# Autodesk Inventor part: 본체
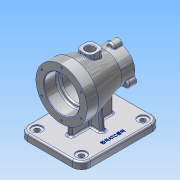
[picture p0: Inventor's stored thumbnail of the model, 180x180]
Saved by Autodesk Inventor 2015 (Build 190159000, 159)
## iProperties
Created: 2021-10
Part Number: 본체
Material: 알루미늄 6061
Document SubType Name: Modeling
Designer: 101256544
Density: 2.7 g/cm^3
Appearance: 알루미늄 - 평지
Mass: 1223.16 g
Surface Area: 900.075 cm^2
Volume: 453.022 cm^3
Author: 101256544
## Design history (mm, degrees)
sketch "스케치1"
  geometry: L1 (0, 77.575)-(0, -77.575); L2 (0, 50)-(45, 50); L3 (45, 50)-(45, 30); L4 (45, 30)-(29, -27); L5 (29, -27)-(29, -50); L6 (29, -50)-(0, -50); L7 (0, 50)-(0, -50); L8 (17.773, 50)-(17.773, -50); 3 further points
  constraints: 16 end point, 4 point on line, 3 perpendicular, 2 midpoint, 1 coincident, 1 collinear, 1 horizontal, 1 horizontal alignment, 1 parallel, 1 vertical
  dimensions: "d0" = 90 diameter of L3 L1; "d1" = 58 diameter of L5 L1; "d2" = 100 vertical distance of L5.end L2.end; "d3" = 20 distance of L2.end L3.end; "d4" = 23 distance of L4.end L5.end
revolve "회전1" sketch "스케치1" stored, may be unused: angle "d5" = 90 deg
sketch "스케치2"
  geometry: L1 (0, 68.61)-(0, -68.61); L2 (-45, 50)-(45, 50) reference; L3 (-29, -50)-(29, -50) reference; L4 (0, 50)-(31, 50); L5 (31, 50)-(31, 27); L6 (31, 27)-(0, 27); L7 (0, 27)-(0, 50); L8 (0, 27)-(25, 27); L9 (25, 27)-(25, -20); L10 (25, -20)-(0, -20); L11 (0, -20)-(0, 27); L12 (0, -20)-(19, -20); L13 (19, -20)-(19, -50); L14 (19, -50)-(0, -50); L15 (0, -50)-(0, -20); 2 further points
  constraints: 26 end point, 6 parallel, 3 horizontal, 3 perpendicular, 2 midpoint, 1 coincident, 1 point on line, 1 vertical
  dimensions: "d6" = 62 diameter of L5 L1; "d7" = 50 diameter of L9 L1; "d9" = 38 diameter of L13 L1; "d10" = 23 distance of L4.end L5.end; "d11" = 47 distance of L8.end L9.end
revolve "회전2" sketch "스케치2" stored, may be unused: angle "d12" = 90 deg
sketch "스케치3" dims "d13" = 80
  geometry: C1 r 31 at (0, 0) reference; C2 r 45 at (0, 0) reference; 2 further points
  constraints: 2 vertical alignment, 1 coincident, 2 other
hole "구멍1" sketch "스케치3" at (0, 40) diameter "d14" = 3.242; stored, may be unused: countersink angle "d18" = 90 deg, drill point angle "d20" = 118 deg; dims "d15" = 9, "d16" = 4, "d17" = 2, "d19" = 11
sketch "스케치4"
  geometry: C1 r 19 at (0, 0) reference; C2 r 7 at (0, 29); 2 further points
  constraints: 2 vertical alignment, 1 centre point, 1 coincident, 1 other
  dimensions: "d24" = 14 diameter of C2
extrude "돌출1" join sketch "스케치4" distance "d25" = 15; taper "d26" = 0 deg
hole "구멍2" sketch "스케치4" diameter "d27" = 3.242; stored, may be unused: countersink angle "d31" = 90 deg, drill point angle "d33" = 118 deg; dims "d28" = 9, "d29" = 4, "d30" = 2, "d32" = 11
node "작업 평면1"
sketch "스케치5"
  geometry: L1 (-45, 50)-(45, 50) reference; L2 (6.949, -50)-(29, -50) reference; L3 (55, 70)-(-55, 70); L4 (-55, 70)-(-55, -70); L5 (-55, -70)-(55, -70); L6 (55, -70)-(55, 70); 3 further points
  constraints: 8 end point, 2 parallel, 1 horizontal, 1 midpoint, 1 perpendicular, 1 vertical alignment
  dimensions: "d38" = 140 distance of L5.end L3.start; "d39" = 110 distance of L3.start L3.end; "d40" = 20 distance between parallel lines of L3 L1
extrude "돌출2" join sketch "스케치5" distance "d41" = 12; taper "d42" = 0 deg
sketch "스케치6"
  geometry: L1 (4, -37)-(-4, -37); L2 (-4, -37)-(-4, 37); L3 (-4, 37)-(4, 37); L4 (4, 37)-(4, -37); L5 (4, -37)-(-4, 37); L6 (-4, -37)-(4, 37); L7 (24, 4)-(-24, 4); L8 (-24, 4)-(-24, -4); L9 (-24, -4)-(24, -4); L10 (24, -4)-(24, 4); L11 (24, 4)-(-24, -4); L12 (-24, 4)-(24, -4); 1 further point
  constraints: 24 end point, 4 midpoint, 4 parallel, 2 horizontal, 2 perpendicular
  dimensions: "d43" = 8 distance of L7.end L8.end; "d44" = 8 distance of L2.end L3.end; "d45" = 74 distance of L3.end L1.start; "d46" = 24 distance from line of L8 point (0, 0); "d47" = 24 distance from line of L10 point (0, 0) (derived)
extrude "돌출3" join sketch "스케치6" stored distance "d48" = 12; taper "d49" = 0 deg
feature "면 기울기1" dims angle "d50" = 5 deg
feature "면 기울기2" dims angle "d51" = 5 deg
node "작업 평면2"
sketch "스케치7"
  geometry: L1 (-12.5, 12.5)-(12.5, 12.5); L2 (12.5, 12.5)-(12.5, -12.5); L3 (12.5, -12.5)-(-12.5, -12.5); L4 (-12.5, -12.5)-(-12.5, 12.5); L5 (-12.5, 12.5)-(12.5, -12.5); L6 (12.5, 12.5)-(-12.5, -12.5); 2 further points
  constraints: 12 end point, 2 midpoint, 2 parallel, 1 coincident, 1 horizontal, 1 perpendicular
  dimensions: "d53" = 25 distance of L2.end L3.end; "d54" = 25 distance of L1.end L2.end
extrude "돌출4" join sketch "스케치7" stored distance "d55" = 12; taper "d56" = 0 deg
hole "구멍3" sketch "스케치7" diameter "d57" = 15; stored, may be unused: countersink angle "d61" = 90 deg, drill point angle "d63" = 118 deg; dims "d58" = 9, "d59" = 4, "d60" = 2, "d62" = 30
chamfer "모따기1" distance "d64" = 1; stored, may be unused: second distance "d65" = 2, angle "d66" = 45 deg
fillet "모깎기1" dims "d67" = 3, "d68" = 16, "d69" = 8
fillet "모깎기2" dims "d70" = 3, "d71" = 1
sketch "스케치8"
  geometry: A1 r 13 centre (39, -54) between (39, -67) and (52, -54) reference; A2 r 13 centre (39, 54) between (52, 54) and (39, 67) reference; A3 r 13 centre (-39, 54) between (-39, 67) and (-52, 54) reference; A4 r 13 centre (-39, -54) between (-52, -54) and (-39, -67) reference; 5 further points
  constraints: 4 coincident
hole "구멍4" sketch "스케치8" at (-39, -54), (-39, 54), (39, -54), (39, 54) diameter "d72" = 9; stored, may be unused: countersink angle "d76" = 90 deg, drill point angle "d78" = 118 deg; dims "d73" = 9, "d74" = 18, "d75" = 2, "d77" = 10
sketch "스케치9"
  geometry: L1 (55, -54)-(55, 54) reference; 2 further points
  constraints: 1 horizontal alignment, 1 other
  dimensions: "d79" = 15 distance from line of L1 point (40, 0)
feature "엠보싱1" sketch "스케치9" dims "d0" = 90, "d1" = 58, "d2" = 100, "d3" = 20, "d4" = 23, "d6" = 62, "d7" = 50, "d9" = 38, "d10" = 23, "d11" = 47, "d80" = 0.5, "d81" = 0
node "솔리드1"
pattern_circular "원형 패턴1" dims angle "d22" = 360 deg
pattern_circular "원형 패턴2" dims angle "d35" = 360 deg
other parameters: "d37" = -82, "d52" = 45
